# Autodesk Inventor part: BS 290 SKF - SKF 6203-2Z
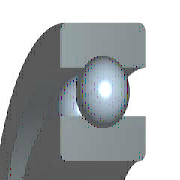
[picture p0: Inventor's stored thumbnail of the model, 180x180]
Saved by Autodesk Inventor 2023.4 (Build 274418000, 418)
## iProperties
Created: 2022-02
Part Number: BS 290 SKF - SKF 6203-2Z
Material: Acier, doux
Description: Roulements à une rangée de billes à gorge profonde avec deux flasques Z SKF
Document SubType Name: Modeling
Standard: BS 290 SKF
Designer: bruno
Standards Organization: BSI
Language: fr-FR
Size Designation: SKF 6203-2Z
Categories: <MemberInstance><Categories><Category DisplayName="Pièces d'arbre" InternalName="7f7aeb1f-a693-4053-b835-cee3144e0d98" Mnemonic="SHFT"><Category DisplayName="Ro
Density: 7.85 g/cm^3
Appearance: Semi-poli
IsCustomPart: 0
Author: bruno
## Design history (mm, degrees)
node "WorkPoint1"
node "WorkAxis1"
node "WorkPlane3"
node "WorkPlane4"
node "WorkPoint2"
pattern_circular "RéseauPolaire1" dims "d17" = 65.95652 (= msp_pocet), angle "d19" = 360 deg
body "Solid1"
node "Esquisse1"
revolve "Révolution1" stored, may be unused: angle "d6" = 360 deg
revolve "Révolution2" stored, may be unused: angle "d10" = 360 deg
node "Esquisse4"
revolve "Révolution3" stored, may be unused: angle "d16" = 360 deg
fillet "Congé1" dims "d20" = 0.6 (= r)
sketch "Esquisse2"
  geometry: L1 (8.5, 12)-(20, 12); L2 (8.5, 0)-(8.5, 12); L3 (20, 0)-(8.5, 0); L4 (20, 12)-(20, 0); L5 (0, 0)-(0, 20); L6 (0, 0)-(0, 20); L7 (-7.2, 0)-(43.2, 0) reference
  constraints: 12 end point, 3 vertical, 2 horizontal, 1 collinear, 1 other
  dimensions: "d1" = 17 diameter of L1.start L5 (= Diam); "d3" = 40 diameter of L1.end L5 (= DD); "d5" = 12 distance of L2.start L1.start (= msp_mdtd2)
sketch "Esquisse3"
  geometry: L1 (16.32, 12)-(16.32, 8.76); L2 (12.18, 12)-(16.32, 12); L3 (12.18, 8.76)-(12.18, 12); L4 (12.18, 0)-(12.18, 3.24); L5 (16.32, 0)-(12.18, 0); L6 (16.32, 3.24)-(16.32, 0); L7 (20, 0)-(-20, 0) reference; L8 (20, 12)-(-20, 12) reference; L9 (0, -42.29)-(0, 61.29); L10 (0, 82.007)-(0, -63.007) reference; A1 r 3.45 centre (14.25, 6) between (16.32, 3.24) and (16.32, 8.76); A2 r 3.45 centre (14.25, 6) between (12.18, 8.76) and (12.18, 3.24)
  constraints: 14 end point, 4 collinear, 4 point on circle, 4 vertical, 2 centre point, 2 concentric, 2 horizontal, 2 point on line
  dimensions: "d9" = 6.9 diameter of A1 (= msp_mdtd6); "d21" = 12.18 distance between parallel lines of L9 L4 (= 0.5 x msp_d1); "d22" = 14.25 distance from line of L9 A1.centre (= 0.5 x msp_ds); "d23" = 16.32 distance between parallel lines of L9 L6 (= 0.5 x msp_dd1)
sketch "Esquisse5"
  geometry: L1 (14.25, 2.55)-(14.25, 9.45); L2 (16.32, 0)-(-16.32, 0) reference; L3 (14.25, 2.55)-(14.25, 9.45); A1 r 3.45 centre (14.25, 6) between (14.25, 2.55) and (14.25, 9.45); A2 r 3.45 centre (14.25, 6) between (16.32, 3.24) and (16.32, 8.76) reference
  constraints: 4 end point, 2 point on circle, 1 centre point, 1 concentric, 1 vertical
  dimensions: "d13" = 0 horizontal distance of A1.centre L1.start; "d15" = 6.9001 diameter of A1 (computed from msp_mdtd6)
other parameters: "Diam" = 17 [user parameter; used in 3 equation terms], "DD" = 40 [user parameter; used in 3 equation terms], "B" = 12 [user parameter; used in 1 equation term], "r" = 0.6 [user parameter; used in 1 equation term], "msp_ds" = 28.5 (= 0.5 x Diam + 0.5 x DD) [user parameter; used in 5 equation terms], "msp_d0" = 6.9 (= -0.3 x Diam + 0.3 x DD) [user parameter; used in 4 equation terms], "msp_d1" = 24.36 (= msp_ds - 0.6 x msp_d0) [user parameter; used in 1 equation term], "msp_dd1" = 32.64 (= msp_ds + 0.6 x msp_d0) [user parameter; used in 1 equation term], "msp_pom" = 42.75 (= 1.5 x msp_ds) [user parameter; used in 1 equation term], "msp_mdtd2" = 12 (= B) [user parameter; used in 3 equation terms], "msp_mdtd4" = 28.5 (= msp_ds) [user parameter], "msp_mdtd6" = 6.9 (= msp_d0) [user parameter; used in 2 equation terms], "msp_mdtd7" = 6 (= 0.5 x msp_mdtd2) [user parameter], "msp_pocet" = 65.95652 (computed from msp_d0, msp_pom) [user parameter; used in 1 equation term], "d2" = 72 (derived), "d4" = 19 (derived), "d7" = 0, "d8" = 15.6 (derived), "d11" = -12 (computed from msp_mdtd2), "d12" = 0 (derived), "d14" = 15.6001 (derived), "d26" = 0, "d27" = 0, "d28" = 0, "d29" = 0, "d30" = 0
